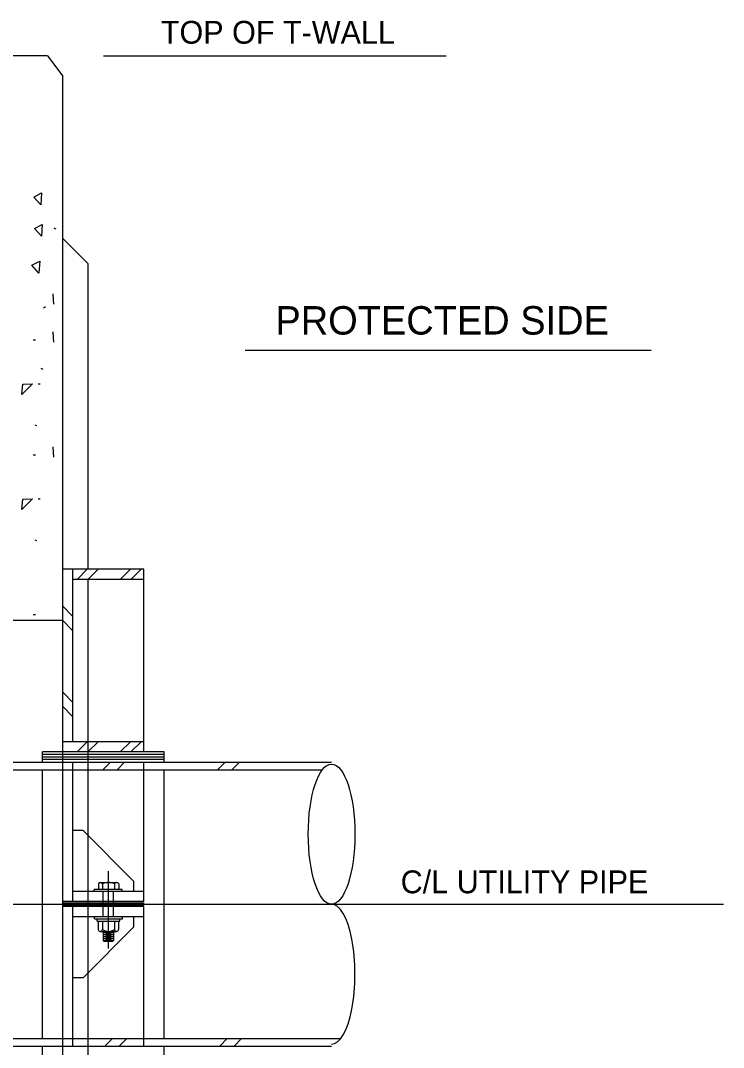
# Model space of a CAD drawing. Extents: x 22388.1 to 22405.7, y 22369.6 to 22390.4.
# Drawn here: x 22394.947 to 22396.39, y 22387.97 to 22390.079 of the extents above; entities that cross this region are included whole.
import ezdxf

# ---------------------------------------------------------------- set-up
doc = ezdxf.new("R2010")
doc.units = 0
for name, color, linetype in [('Level 1', 7, 'Continuous'), ('Level 10', 7, 'Continuous'), ('Level 2', 7, 'Continuous'), ('Level 3', 7, 'Continuous'), ('Level 4', 7, 'Continuous'), ('Level 44', 7, 'Continuous'), ('Level 50', 7, 'Continuous'), ('Level 7', 7, 'Continuous')]:
    doc.layers.add(name, color=color, linetype=linetype)

msp = doc.modelspace()

# ---------------------------------------------------------------- linework, layer by layer
at = {"layer": 'Level 1'}
for p, q in [((22395.117, 22390.0059), (22395.8211, 22390.0059)), ((22395.0632, 22388.9309), (22395.084, 22388.9518)), ((22395.0853, 22388.9309), (22395.1061, 22388.9518)), ((22395.1516, 22388.9309), (22395.1724, 22388.9518)), ((22395.1737, 22388.9309), (22395.1945, 22388.9518)), ((22395.0543, 22388.8552), (22395.0335, 22388.8761)), ((22395.0543, 22388.8258), (22395.0335, 22388.8466)), ((22395.0543, 22388.6784), (22395.0335, 22388.6993)), ((22395.0543, 22388.649), (22395.0335, 22388.6698)), ((22395.0632, 22388.5768), (22395.084, 22388.5976)), ((22395.0853, 22388.5768), (22395.1061, 22388.5976)), ((22395.1516, 22388.5768), (22395.1724, 22388.5976)), ((22395.1737, 22388.5768), (22395.1945, 22388.5976)), ((22395.2418, 22388.5716), (22394.9918, 22388.5716)), ((22395.2418, 22388.5664), (22394.9918, 22388.5664)), ((22395.2418, 22388.5611), (22394.9918, 22388.5611)), ((22395.1156, 22388.5403), (22395.1313, 22388.5559)), ((22395.1451, 22388.5403), (22395.1607, 22388.5559)), ((22395.3513, 22388.5403), (22395.367, 22388.5559)), ((22395.3808, 22388.5403), (22395.3964, 22388.5559)), ((22395.1273, 22388.1735), (22395.1273, 22388.3321)), ((22395.111, 22388.3088), (22395.1443, 22388.3088)), ((22395.1556, 22388.2942), (22395.0984, 22388.2942)), ((22395.0984, 22388.2903), (22395.0984, 22388.2942)), ((22395.1068, 22388.306), (22395.1068, 22388.2942)), ((22395.1154, 22388.3061), (22395.1154, 22388.2942)), ((22395.1169, 22388.2382), (22395.1169, 22388.2903)), ((22395.1377, 22388.2382), (22395.1377, 22388.2903)), ((22395.14, 22388.306), (22395.14, 22388.2942)), ((22395.1485, 22388.306), (22395.1485, 22388.2942)), ((22395.1556, 22388.2903), (22395.1556, 22388.2942)), ((22395.0335, 22388.2669), (22395.2001, 22388.2669)), ((22395.2001, 22388.2617), (22395.2001, 22388.2669)), ((22393.4995, 22388.2643), (22396.3902, 22388.2643)), ((22395.0335, 22388.2617), (22395.2001, 22388.2617)), ((22395.0987, 22388.2343), (22395.0987, 22388.2382)), ((22395.0987, 22388.2343), (22395.156, 22388.2343)), ((22395.1039, 22388.2291), (22395.1039, 22388.2343)), ((22395.1039, 22388.2291), (22395.1508, 22388.2291)), ((22395.1065, 22388.2291), (22395.1065, 22388.2125)), ((22395.1151, 22388.2291), (22395.1151, 22388.2125)), ((22395.1397, 22388.2291), (22395.1397, 22388.2125)), ((22395.1481, 22388.2291), (22395.1481, 22388.2125)), ((22395.1508, 22388.2291), (22395.1508, 22388.2343)), ((22395.156, 22388.2343), (22395.156, 22388.2382)), ((22395.1107, 22388.2083), (22395.144, 22388.2083)), ((22395.1169, 22388.2083), (22395.1169, 22388.1895)), ((22395.1169, 22388.2062), (22395.1377, 22388.2062)), ((22395.1221, 22388.2041), (22395.133, 22388.2041)), ((22395.1377, 22388.2083), (22395.1377, 22388.1896)), ((22395.1169, 22388.202), (22395.1377, 22388.202)), ((22395.1169, 22388.1978), (22395.1377, 22388.1978)), ((22395.1169, 22388.1937), (22395.1377, 22388.1937)), ((22395.1169, 22388.1895), (22395.118, 22388.1885)), ((22395.1169, 22388.1895), (22395.1377, 22388.1895)), ((22395.118, 22388.1885), (22395.1367, 22388.1885)), ((22395.1221, 22388.1999), (22395.133, 22388.1999)), ((22395.1221, 22388.1958), (22395.133, 22388.1958)), ((22395.1221, 22388.1916), (22395.133, 22388.1916)), ((22395.1377, 22388.1896), (22395.1367, 22388.1885)), ((22395.1201, 22387.9726), (22395.1357, 22387.9882)), ((22395.1495, 22387.9726), (22395.1651, 22387.9882)), ((22395.3558, 22387.9726), (22395.3714, 22387.9882)), ((22395.3852, 22387.9726), (22395.4008, 22387.9882))]:
    msp.add_line(p, q, dxfattribs=at)
for centre, radius, start, end in [((22395.1111, 22388.3041), 0.00469, 24.0009, 156.8325), ((22395.1276, 22388.2803), 0.0285, 64.116, 115.4481), ((22395.1443, 22388.3042), 0.00456, 22.8005, 157.625), ((22395.1107, 22388.2125), 0.00422, 180.5659, 359.4341), ((22395.1274, 22388.2286), 0.0203, 232.4343, 307.5657), ((22395.1439, 22388.2125), 0.00421, 180.4975, 359.5025)]:
    msp.add_arc(centre, radius, start, end, dxfattribs=at)
msp.add_ellipse((22395.5855, 22388.408), major_axis=(0, 0.1438), ratio=0.333333, dxfattribs=at)
msp.add_ellipse((22395.5855, 22388.1205), major_axis=(0, -0.1438), ratio=0.333333, start_param=0, end_param=3.141593, dxfattribs=at)
at = {"layer": 'Level 10'}
msp.add_line((22396.2419, 22389.4013), (22395.4081, 22389.4013), dxfattribs=at)
at = {"layer": 'Level 2'}
for p, q in [((22395.2001, 22388.9518), (22395.0335, 22388.9518)), ((22395.0335, 22388.5768), (22395.0335, 22388.9518)), ((22395.0543, 22388.5976), (22395.0543, 22388.9518)), ((22395.2001, 22388.5768), (22395.2001, 22388.9518)), ((22395.2001, 22388.9309), (22395.0543, 22388.9309)), ((22395.2001, 22388.5976), (22395.0335, 22388.5976)), ((22395.2418, 22388.5768), (22394.9918, 22388.5768)), ((22394.9918, 22388.5559), (22394.9918, 22388.5768)), ((22395.2418, 22388.5559), (22395.2418, 22388.5768)), ((22393.8376, 22388.5403), (22395.5668, 22388.5403)), ((22393.8564, 22388.5559), (22395.5855, 22388.5559)), ((22394.9918, 22387.9882), (22394.9918, 22388.5403)), ((22395.0335, 22388.2695), (22395.0335, 22388.5559)), ((22395.0543, 22388.2695), (22395.0543, 22388.5559)), ((22395.2001, 22388.2695), (22395.2001, 22388.5559)), ((22395.2418, 22387.9882), (22395.2418, 22388.5403)), ((22395.0752, 22388.4153), (22395.0544, 22388.4153)), ((22395.1794, 22388.3111), (22395.0752, 22388.4153)), ((22395.1794, 22388.2903), (22395.1794, 22388.3111)), ((22395.2001, 22388.2903), (22395.0543, 22388.2903)), ((22395.2001, 22388.2695), (22395.0335, 22388.2695)), ((22395.2001, 22388.2591), (22395.0335, 22388.2591)), ((22395.0335, 22387.9726), (22395.0335, 22388.2591)), ((22395.0543, 22387.9726), (22395.0543, 22388.2591)), ((22395.2001, 22387.9726), (22395.2001, 22388.2591)), ((22395.2001, 22388.2382), (22395.0543, 22388.2382)), ((22395.1794, 22388.2174), (22395.1794, 22388.2382)), ((22395.1794, 22388.2174), (22395.0752, 22388.1132)), ((22395.0752, 22388.1132), (22395.0544, 22388.1132)), ((22393.8564, 22387.9726), (22395.5855, 22387.9726)), ((22393.8751, 22387.9882), (22395.6043, 22387.9882)), ((22394.9918, 22387.9518), (22394.9918, 22387.9726)), ((22395.2418, 22387.9518), (22395.2418, 22387.9726))]:
    msp.add_line(p, q, dxfattribs=at)
at = {"layer": 'Level 3'}
msp.add_line((22395.0752, 22388.1132), (22395.0752, 22388.1132), dxfattribs=at)
at = {"layer": 'Level 44'}
for p, q in [((22395.0155, 22389.6528), (22395.0195, 22389.6508)), ((22394.9942, 22389.4889), (22394.998, 22389.4911)), ((22394.9731, 22389.423), (22394.9776, 22389.423)), ((22394.9885, 22389.365), (22394.9925, 22389.363)), ((22394.9828, 22389.3329), (22394.987, 22389.3329)), ((22394.9762, 22389.2485), (22394.9795, 22389.2473)), ((22394.9731, 22389.1868), (22394.9776, 22389.1868)), ((22394.9828, 22389.0966), (22394.987, 22389.0966)), ((22394.9762, 22389.0123), (22394.9795, 22389.011)), ((22394.9731, 22388.8588), (22394.9776, 22388.8588))]:
    msp.add_line(p, q, dxfattribs=at)
for points in [[(22394.9884, 22389.7002), (22394.9741, 22389.7162), (22394.99, 22389.7247)], [(22394.9899, 22389.6356), (22394.9757, 22389.6516), (22394.9916, 22389.6601)], [(22394.9845, 22389.56), (22394.9703, 22389.576), (22394.9862, 22389.5845)], [(22394.9515, 22389.3318), (22394.9715, 22389.3329), (22394.9499, 22389.3107)], [(22394.9515, 22389.0955), (22394.9715, 22389.0966), (22394.9499, 22389.0744)]]:
    msp.add_lwpolyline(points, close=True, dxfattribs=at)
for points in [[(22395.0143, 22389.5159), (22395.0131, 22389.5169), (22395.0143, 22389.4963)], [(22395.0143, 22389.438), (22395.0131, 22389.439), (22395.0143, 22389.4184)], [(22395.0143, 22389.2018), (22395.0131, 22389.2028), (22395.0143, 22389.1821)]]:
    msp.add_lwpolyline(points, dxfattribs=at)
at = {"layer": 'Level 50'}
msp.add_line((22395.1481, 22388.2125), (22395.1481, 22388.2125), dxfattribs=at)
at = {"layer": 'Level 7'}
for p, q in [((22395.0022, 22390.0059), (22394.5647, 22390.0059)), ((22395.0022, 22390.0059), (22395.0335, 22389.9643)), ((22395.0335, 22388.5559), (22395.0335, 22389.9643)), ((22395.0335, 22389.6309), (22395.0855, 22389.5789)), ((22395.0855, 22388.9518), (22395.0855, 22389.5789)), ((22395.0855, 22387.5976), (22395.0855, 22388.9309)), ((22394.5335, 22388.8476), (22395.0335, 22388.8476)), ((22395.0335, 22387.9882), (22395.0335, 22388.5403)), ((22395.0335, 22386.2627), (22395.0335, 22387.9726))]:
    msp.add_line(p, q, dxfattribs=at)

# ---------------------------------------------------------------- texts
at = {"layer": 'Level 10'}
msp.add_text('PROTECTED SIDE', height=0.058333, dxfattribs=at).set_placement((22395.4702, 22389.4338))
at = {"layer": 'Level 4'}
for s, p in [('TOP OF T-WALL', (22395.235, 22390.031)), ('C/L UTILITY PIPE', (22395.7274, 22388.2866))]:
    msp.add_text(s, height=0.046875, dxfattribs=at).set_placement(p)

doc.saveas('drawing.dxf')
